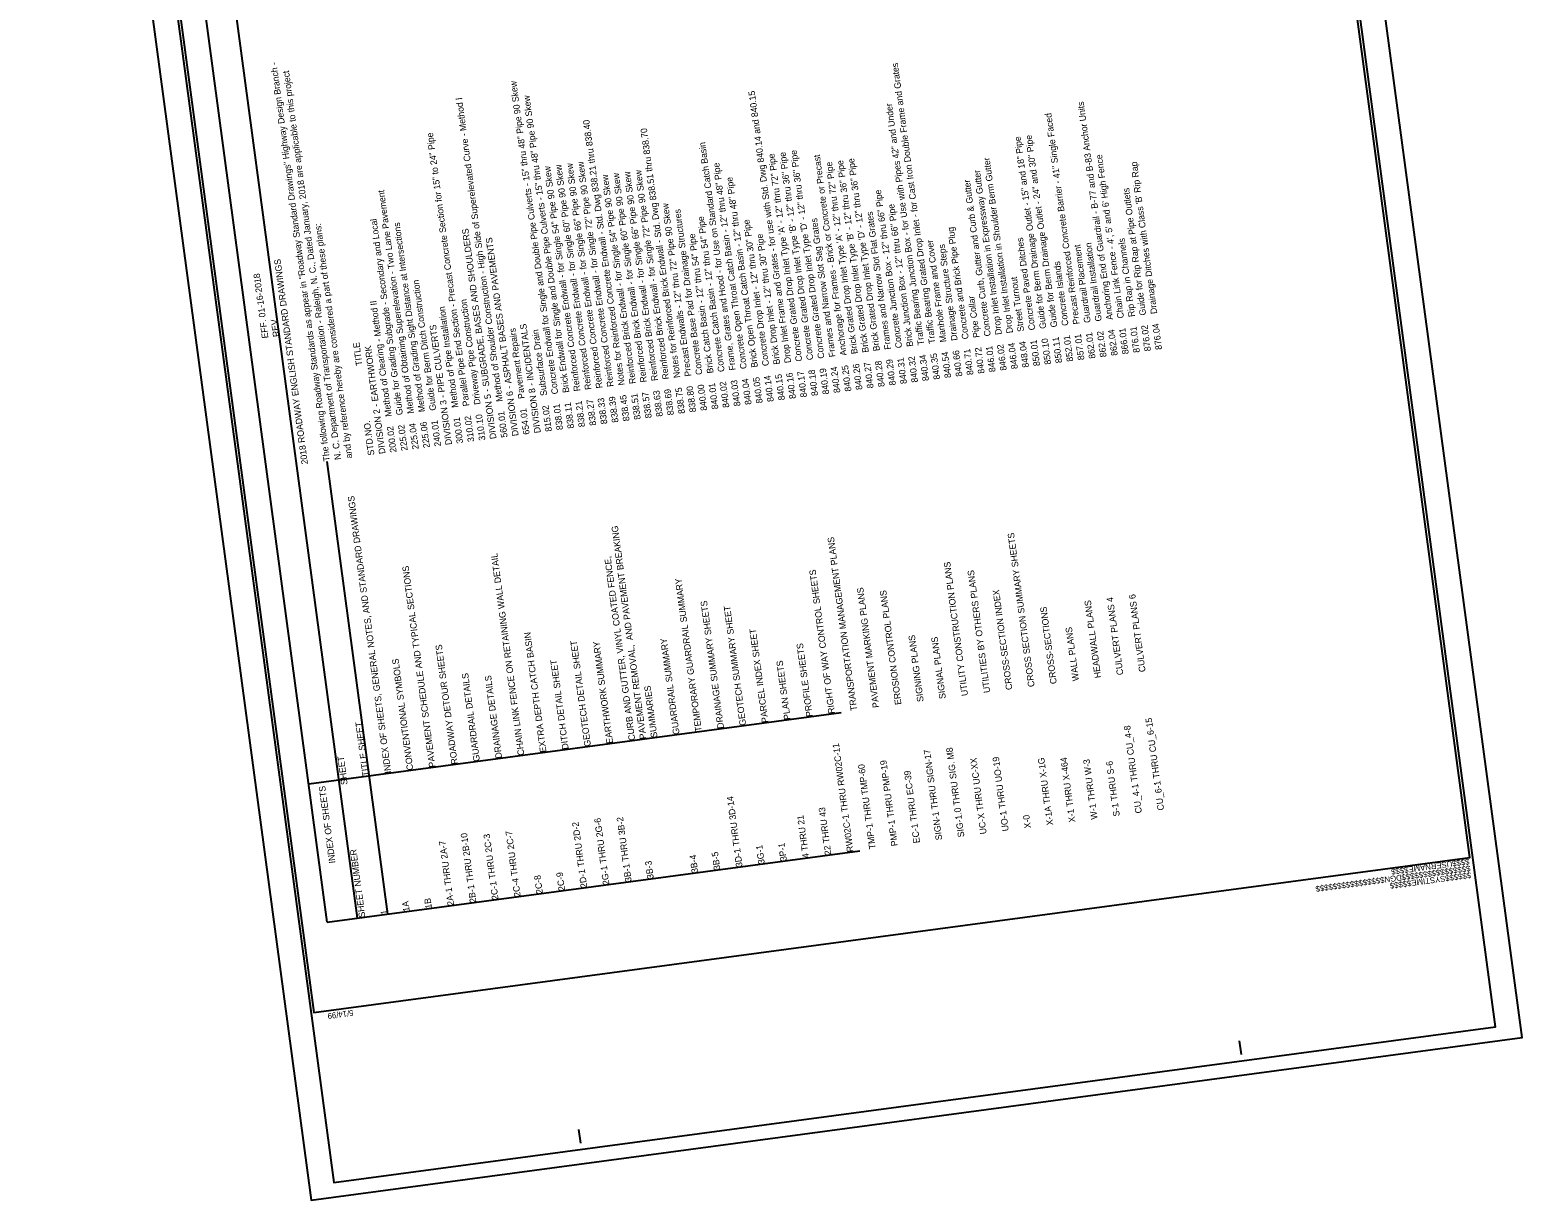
# Model space of a CAD drawing. Extents: x 2573931 to 2578852, y 980053 to 983667.
# Drawn here: x 2573931 to 2575543, y 980964 to 982228 of the extents above; entities that cross this region are included whole.
import ezdxf

# ---------------------------------------------------------------- set-up
doc = ezdxf.new("R2010")
doc.units = 0
for name, color, linetype in [('Scratch_Level_1', 7, 'Continuous'), ('Sheet Border Standard 30in CELL', 7, 'Continuous'), ('Sheet Data Text CELL', 7, 'Continuous'), ('Sheet Plot Border Inside CELL', 7, 'Continuous'), ('Sheet Plot Border Outside CELL', 7, 'Continuous')]:
    doc.layers.add(name, color=color, linetype=linetype)

msp = doc.modelspace()

# ---------------------------------------------------------------- linework, layer by layer
at = {"layer": 'Scratch_Level_1'}
for p, q in [((2574252.3, 981264.1), (2573931, 983659.8)), ((2574284.8, 981268.5), (2573963.1, 983666.7)), ((2574251.9, 981761.8), (2574317.4, 981272.9)), ((2574232.3, 981413.5), (2574807.5, 981490.7)), ((2574252.3, 981264.1), (2574827.5, 981341.3))]:
    msp.add_line(p, q, dxfattribs=at)
at = {"layer": 'Sheet Border Standard 30in CELL'}
for p, q in [((2574237.7, 981167.9), (2574237.7, 981167.9)), ((2575239.8, 981121.3), (2575237.8, 981136.1)), ((2574526.2, 981025.6), (2574524.2, 981040.4))]:
    msp.add_line(p, q, dxfattribs=at)
msp.add_lwpolyline([(2573998.6, 982950.7), (2574237.9, 981166.7), (2575486.7, 981334.2), (2575247.4, 983118.2)], close=True, dxfattribs=at)
at = {"layer": 'Sheet Plot Border Inside CELL'}
msp.add_lwpolyline([(2573993.5, 982965.2), (2574259.4, 980983.1), (2575514.3, 981151.4), (2575248.4, 983133.5)], close=True, dxfattribs=at)
at = {"layer": 'Sheet Plot Border Outside CELL'}
msp.add_lwpolyline([(2573966.1, 982967), (2574234.8, 980964.1), (2575543, 981139.6), (2575274.4, 983142.4)], close=True, dxfattribs=at)

# ---------------------------------------------------------------- texts
at = {"layer": 'Sheet Border Standard 30in CELL'}
for s, p in [('$$$$$$$$$$$$$$$$DGN$$$$$$$$$$$$$$$$', (2575486.8, 981325.6)), ('$$$$USERNAME$$$$', (2575485.7, 981333)), ('$$$$$$SYSTIME$$$$$', (2575487.5, 981318.3)), ('5/14/99', (2574280.1, 981169.6))]:
    msp.add_text(s, height=6.3, rotation=187.639, dxfattribs=at).set_placement(p)
at = {"layer": 'Sheet Data Text CELL'}
for s, p in [('The following Roadway Standards as appear in "Roadway Standard Drawings" Highway Design Branch -', (2574255.3, 981762.3)), ('N. C. Department of Transportation - Raleigh, N. C., Dated January, 2018 are applicable to this project', (2574267.3, 981763.9)), ('840.35    Traffic Bearing Grated Drop Inlet - for Cast Iron Double Frame and Grates', (2574914.4, 981850.7)), ('838.01    Concrete Endwall for Single and Double Pipe Culverts - 15" thru 48" Pipe 90 Skew', (2574507, 981796.1)), ('840.16    Drop Inlet Frame and Grates - for use with Std. Dwg 840.14 and 840.15', (2574758.6, 981829.8)), ('560.01    Method of Shoulder Construction - High Side of Superelevated Curve - Method I', (2574447.1, 981788)), ('838.11    Brick Endwall for Single and Double Pipe Culverts - 15" thru 48" Pipe 90 Skew', (2574519, 981797.7)), ('840.34    Traffic Bearing Junction Box - for Use with Pipes 42" and Under', (2574902.4, 981849.1)), ('862.04    Anchoring End of Guardrail - B-77 and B-83 Anchor Units', (2575106.2, 981876.4)), ('838.45    Notes for Reinforced Concrete Endwall - Std. Dwg 838.21 thru 838.40', (2574578.9, 981805.7)), ('857.01    Precast Reinforced Concrete Barrier - 41" Single Faced', (2575070.2, 981871.6)), ('310.02    Parallel Pipe End Section - Precast Concrete Section for 15" to 24" Pipe', (2574411.1, 981783.2)), ('838.75    Notes for Reinforced Brick Endwall - Std. Dwg 838.51 thru 838.70', (2574638.8, 981813.7)), ('850.10    Guide for Berm Drainage Outlet - 15" and 18" Pipe', (2575034.3, 981866.8)), ('850.11    Guide for Berm Drainage Outlet - 24" and 30" Pipe', (2575046.2, 981868.4)), ('840.03    Frame, Grates and Hood - for Use on Standard Catch Basin', (2574698.7, 981821.8)), ('840.19    Concrete Grated Drop Inlet Type \'D\' - 12" thru 36" Pipe', (2574794.6, 981834.6)), ('838.21    Reinforced Concrete Endwall - for Single 54" Pipe 90 Skew', (2574530.9, 981799.3)), ('838.27    Reinforced Concrete Endwall - for Single 60" Pipe 90 Skew', (2574542.9, 981800.9)), ('838.33    Reinforced Concrete Endwall - for Single 66" Pipe 90 Skew', (2574554.9, 981802.5)), ('838.39    Reinforced Concrete Endwall - for Single 72" Pipe 90 Skew', (2574566.9, 981804.1)), ('840.04    Concrete Open Throat Catch Basin - 12" thru 48" Pipe', (2574710.7, 981823.4)), ('840.17    Concrete Grated Drop Inlet Type \'A\' - 12" thru 72" Pipe', (2574770.6, 981831.4)), ('840.18    Concrete Grated Drop Inlet Type \'B\' - 12" thru 36" Pipe', (2574782.6, 981833)), ('840.25    Anchorage for Frames - Brick or Concrete or Precast', (2574818.6, 981837.8)), ('840.26    Brick Grated Drop Inlet Type \'A\' - 12" thru 72" Pipe', (2574830.5, 981839.5)), ('840.27    Brick Grated Drop Inlet Type \'B\' - 12" thru 36" Pipe', (2574842.5, 981841.1)), ('840.28    Brick Grated Drop Inlet Type \'D\' - 12" thru 36" Pipe', (2574854.5, 981842.7)), ('846.04    Drop Inlet Installation in Shoulder Berm Gutter', (2574998.3, 981862)), ("866.01    Chain Link Fence - 4', 5' and 6' High Fence", (2575118.1, 981878)), ("876.04    Drainage Ditches with Class 'B' Rip Rap", (2575154.1, 981882.8)), ('838.51    Reinforced Brick Endwall - for Single 54" Pipe 90 Skew', (2574590.9, 981807.3)), ('838.57    Reinforced Brick Endwall - for Single 60" Pipe 90 Skew', (2574602.8, 981808.9)), ('838.63    Reinforced Brick Endwall - for Single 66" Pipe 90 Skew', (2574614.8, 981810.5)), ('838.69    Reinforced Brick Endwall - for Single 72" Pipe 90 Skew', (2574626.8, 981812.1)), ('840.05    Brick Open Throat Catch Basin - 12" thru 48" Pipe', (2574722.7, 981825)), ('846.01    Concrete Curb, Gutter and Curb & Gutter', (2574974.3, 981858.7)), ('846.02    Drop Inlet Installation in Expressway Gutter', (2574986.3, 981860.3)), ('225.04    Method of Obtaining Superelevation - Two Lane Pavement', (2574351.2, 981775.2)), ('840.31    Concrete Junction Box - 12" thru 66" Pipe', (2574878.5, 981845.9)), ('876.02    Guide for Rip Rap at Pipe Outlets', (2575142.1, 981881.2)), ('838.80    Precast Endwalls - 12" thru 72" Pipe 90 Skew', (2574650.8, 981815.3)), ('840.00    Concrete Base Pad for Drainage Structures', (2574662.8, 981817)), ('840.29    Frames and Narrow Slot Flat Grates', (2574866.5, 981844.3)), ('840.32    Brick Junction Box - 12" thru 66" Pipe', (2574890.5, 981847.5)), ('and by reference hereby are considered a part of these plans:', (2574279.3, 981765.5)), ('225.02    Guide for Grading Subgrade - Secondary and Local', (2574339.2, 981773.6)), ('225.06    Method of Grading Sight Distance at Intersections', (2574363.2, 981776.8)), ('840.02    Concrete Catch Basin - 12" thru 54" Pipe', (2574686.7, 981820.2)), ('840.14    Concrete Drop Inlet - 12" thru 30" Pipe', (2574734.7, 981826.6)), ('840.24    Frames and Narrow Slot Sag Grates', (2574806.6, 981836.2)), ('DIVISION 5 - SUBGRADE, BASES AND SHOULDERS', (2574435.1, 981786.4)), ('DIVISION 6 - ASPHALT BASES AND PAVEMENTS', (2574459, 981789.6)), ('840.01    Brick Catch Basin - 12" thru 54" Pipe', (2574674.8, 981818.6)), ('840.15    Brick Drop Inlet - 12" thru 30" Pipe', (2574746.7, 981828.2)), ('840.54    Manhole Frame and Cover', (2574926.4, 981852.3)), ('840.71    Concrete and Brick Pipe Plug', (2574950.4, 981855.5)), ('850.01    Concrete Paved Ditches', (2575022.3, 981865.2)), ('876.01    Rip Rap in Channels', (2575130.1, 981879.6)), ('840.66    Drainage Structure Steps', (2574938.4, 981853.9)), ('862.01    Guardrail Placement', (2575082.2, 981873.2)), ('862.02    Guardrail Installation', (2575094.2, 981874.8)), ('2018 ROADWAY ENGLISH STANDARD DRAWINGS', (2574231.4, 981759.1)), ('852.01    Concrete Islands', (2575058.2, 981870)), ('                                                      EFF. 01-16-2018', (2574207.4, 981755.9)), ('240.01    Guide for Berm Ditch Construction', (2574375.2, 981778.4)), ('848.04    Street Turnout', (2575010.3, 981863.6)), ('200.02    Method of Clearing - Method II', (2574327.2, 981771.9)), ('310.10    Driveway Pipe Construction', (2574423.1, 981784.8)), ('840.72    Pipe Collar', (2574962.4, 981857.1)), ('300.01    Method of Pipe Installation ', (2574399.1, 981781.6)), ('                                                      REV. ', (2574219.4, 981757.5)), ('DIVISION 3 - PIPE CULVERTS', (2574387.1, 981780)), ('654.01    Pavement Repairs', (2574471, 981791.2)), ('DIVISION 8 - INCIDENTALS', (2574483, 981792.8)), ('815.02    Subsurface Drain', (2574495, 981794.4)), ('STD.NO.                       TITLE', (2574303.3, 981768.7)), ('DIVISION 2 - EARTHWORK', (2574315.2, 981770.3)), ('INDEX OF SHEETS, GENERAL NOTES, AND STANDARD DRAWINGS', (2574321.4, 981425.5)), ('PAVEMENT REMOVAL,  AND PAVEMENT BREAKING', (2574597, 981462.4)), ('TRANSPORTATION MANAGEMENT PLANS', (2574824.7, 981493)), ('CROSS SECTION SUMMARY SHEETS', (2575016.4, 981518.7)), ('CHAIN LINK FENCE ON RETAINING WALL DETAIL', (2574465.2, 981444.7)), ('PAVEMENT SCHEDULE AND TYPICAL SECTIONS', (2574369.3, 981431.9)), ('CURB AND GUTTER, VINYL COATED FENCE, ', (2574585, 981460.8)), ('RIGHT OF WAY CONTROL SHEETS', (2574800.7, 981489.8)), ('UTILITY CONSTRUCTION PLANS', (2574944.5, 981509)), ('TEMPORARY GUARDRAIL SUMMARY', (2574656.9, 981470.5)), ('UTILITIES BY OTHERS PLANS', (2574968.5, 981512.3)), ('PAVEMENT MARKING PLANS', (2574848.6, 981496.2)), ('EROSION CONTROL PLANS', (2574872.6, 981499.4)), ('CROSS-SECTION INDEX', (2574992.5, 981515.5)), ('CULVERT PLANS 4', (2575112.3, 981531.5)), ('CULVERT PLANS 6 ', (2575136.3, 981534.8)), ('DRAINAGE SUMMARY SHEETS', (2574680.9, 981473.7)), ('GEOTECH SUMMARY SHEET', (2574704.8, 981476.9)), ('CROSS-SECTIONS', (2575040.4, 981521.9)), ('HEADWALL PLANS', (2575088.3, 981528.3)), ('PARCEL INDEX SHEET', (2574728.8, 981480.1)), ('WALL PLANS', (2575064.4, 981525.1)), ('ROADWAY DETOUR SHEETS', (2574393.3, 981435.1)), ('EXTRA DEPTH CATCH BASIN', (2574489.1, 981448)), ('GEOTECH DETAIL SHEET', (2574537.1, 981454.4)), ('EARTHWORK SUMMARY', (2574561, 981457.6)), ('GUARDRAIL SUMMARY', (2574632.9, 981467.2)), ('PROFILE SHEETS', (2574776.7, 981486.5)), ('SIGNING PLANS', (2574896.6, 981502.6)), ('SIGNAL PLANS', (2574920.5, 981505.8)), ('CONVENTIONAL SYMBOLS', (2574345.3, 981428.7)), ('GUARDRAIL DETAILS', (2574417.2, 981438.3)), ('DITCH DETAIL SHEET', (2574513.1, 981451.2)), ('PLAN SHEETS', (2574752.8, 981483.3)), ('DRAINAGE DETAILS ', (2574441.2, 981441.5)), ('SUMMARIES', (2574609, 981464)), ('CU_6-1 THRU CU_6-15                                               ', (2575156.3, 981385.4)), ('TITLE SHEET', (2574297.4, 981422.2)), ('CU_4-1 THRU CU_4-8', (2575132.3, 981382.2)), ('RW02C-1 THRU RW02C-11   ', (2574820.7, 981340.4)), ('SIG-1.0 THRU SIG. M8', (2574940.6, 981356.4)), ('SHEET NUMBER                           SHEET   ', (2574293.5, 981269.7)), ('PMP-1 THRU PMP-19', (2574868.7, 981346.8)), ('SIGN-1 THRU SIGN-17', (2574916.6, 981353.2)), ('UC-X THRU UC-XX', (2574964.6, 981359.7)), ('UO-1 THRU UO-19', (2574988.5, 981362.9)), ('X-1A THRU X-1G                                                                             ', (2575036.5, 981369.3)), ('X-1 THRU X-464     ', (2575060.4, 981372.5)), ('W-1 THRU W-3', (2575084.4, 981375.7)), ('S-1 THRU S-6', (2575108.4, 981378.9)), ('TMP-1 THRU TMP-60', (2574844.7, 981343.6)), ('EC-1 THRU EC-39', (2574892.6, 981350)), ('                        INDEX OF SHEETS ', (2574269.5, 981266.4)), ('3D-1 THRU 3D-14', (2574700.9, 981324.3)), ('22 THRU 43', (2574796.8, 981337.2)), ('2D-1 THRU 2D-2', (2574533.1, 981301.8)), ('2G-1 THRU 2G-6', (2574557.1, 981305)), ('3B-1 THRU 3B-2', (2574581.1, 981308.2)), ('4 THRU 21', (2574772.8, 981333.9)), ('X-0      ', (2575012.5, 981366.1)), ('2B-1 THRU 2B-10', (2574413.3, 981285.7)), ('2C-1 THRU 2C-3', (2574437.3, 981288.9)), ('2C-4 THRU 2C-7', (2574461.2, 981292.2)), ('2A-1 THRU 2A-7', (2574389.3, 981282.5)), ('3B-5', (2574676.9, 981321.1)), ('3G-1', (2574724.9, 981327.5)), ('3P-1', (2574748.8, 981330.7)), ('3B-3', (2574605, 981311.4)), ('3B-4', (2574653, 981317.9)), ('2C-8', (2574485.2, 981295.4)), ('2C-9', (2574509.2, 981298.6)), ('1B  ', (2574365.4, 981279.3)), ('1', (2574317.4, 981272.9)), ('1A   ', (2574341.4, 981276.1))]:
    msp.add_text(s, height=7, rotation=97.639, dxfattribs=at).set_placement(p)

doc.saveas('drawing.dxf')
